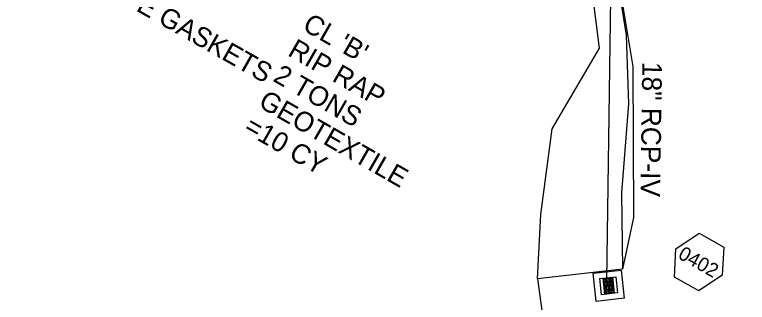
# Model space of a CAD drawing. Extents: x 1116825 to 1117461, y 843538 to 843929.
# Drawn here: x 1116903.7 to 1117034.1, y 843652.8 to 843703.9 of the extents above; entities that cross this region are included whole.
import ezdxf

# ---------------------------------------------------------------- set-up
doc = ezdxf.new("R2010")
doc.units = 0
for name, color, linetype in [('Exist Plan Preparation Watershed Blue', 7, 'Continuous'), ('Exist Plan Preparation Watershed Red', 7, 'Continuous'), ('Prop Drainage Structure Box Number Symbol CELL', 7, 'Continuous'), ('Prop Drainage Structure Drop Inlet Grate 2 Wide Slots and Flat Grates 840 20 TB CELL', 7, 'Continuous'), ('Prop Drainage Structure Pipe CSP Rod and Lug with Sleeve Gaskets Label', 7, 'Continuous'), ('Prop Drainage Structure Pipe RCP 18in Class IV', 7, 'Continuous'), ('Prop Drainage Structure Pipe RCP 18in Class IV Label', 7, 'Continuous'), ('Prop Drainage Structure Plot Symbol 20 Scale', 7, 'Continuous'), ('Prop Drainage Structure Plot Symbol 50 Scale', 7, 'Continuous'), ('Prop Erosion Rip Rap Pad at Outlet Label', 7, 'Continuous')]:
    doc.layers.add(name, color=color, linetype=linetype)

msp = doc.modelspace()

# ---------------------------------------------------------------- linework, layer by layer
at = {"layer": 'Exist Plan Preparation Watershed Blue'}
msp.add_lwpolyline([(1117011.88, 843658.68), (1116996.78, 843656.94), (1116997.38, 843668.37), (1116999.37, 843683.65), (1117007.83, 843698), (1117005.84, 843713.49), (1117010.39, 843713.99), (1117012.55, 843700.29), (1117012.98, 843688.08), (1117011.7, 843672.23)], close=True, dxfattribs=at)
at = {"layer": 'Exist Plan Preparation Watershed Red'}
msp.add_lwpolyline([(1117010.41, 843714.72), (1117013.74, 843694.71), (1117013.85, 843667.87), (1117011.88, 843658.68), (1116996.78, 843656.94), (1116999.95, 843633.96), (1117011.91, 843596.88), (1117025.61, 843575.89), (1117048.71, 843550.16), (1117064.03, 843538.25), (1117084.77, 843547.62), (1117217.35, 843572.44), (1117328.84, 843554.91), (1117432.93, 843571.69), (1117450.5, 843607.65), (1117450.73, 843646.27), (1117460.85, 843746.89), (1117431.96, 843772.25), (1117401.49, 843797.45), (1117287.63, 843757.83), (1117159.59, 843729.38)], close=True, dxfattribs=at)
at = {"layer": 'Prop Drainage Structure Box Number Symbol CELL'}
msp.add_lwpolyline([(1117025.57, 843665.04), (1117029.92, 843662.58), (1117029.66, 843657.58), (1117025.51, 843654.79), (1117021.16, 843657.26), (1117021.42, 843662.25), (1117025.57, 843665.04)], dxfattribs=at)
at = {"layer": 'Prop Drainage Structure Drop Inlet Grate 2 Wide Slots and Flat Grates 840 20 TB CELL'}
for p, q in [((1117009.28, 843657.14), (1117009.28, 843657.14)), ((1117008.6, 843655.62), (1117008.6, 843655.62)), ((1117009.44, 843655.71), (1117009.44, 843655.71)), ((1117010.27, 843655.8), (1117010.27, 843655.8)), ((1117009.59, 843654.28), (1117009.59, 843654.28))]:
    msp.add_line(p, q, dxfattribs=at)
for points in [[(1117010.12, 843657.23), (1117010.43, 843654.37), (1117008.76, 843654.19), (1117008.45, 843657.05), (1117010.12, 843657.23)], [(1117010.08, 843657.18), (1117010.38, 843654.41), (1117008.8, 843654.23), (1117008.5, 843657.01), (1117010.08, 843657.18)], [(1117010.07, 843657.17), (1117010.22, 843655.8), (1117008.65, 843655.63), (1117008.5, 843657), (1117010.07, 843657.17)], [(1117008.84, 843656.98), (1117008.9, 843656.38), (1117008.71, 843656.36), (1117008.64, 843656.96), (1117008.84, 843656.98)], [(1117008.91, 843656.32), (1117008.98, 843655.73), (1117008.78, 843655.7), (1117008.72, 843656.3), (1117008.91, 843656.32)], [(1117009.11, 843657.01), (1117009.18, 843656.41), (1117008.99, 843656.39), (1117008.92, 843656.99), (1117009.11, 843657.01)], [(1117009.19, 843656.35), (1117009.25, 843655.76), (1117009.06, 843655.73), (1117008.99, 843656.33), (1117009.19, 843656.35)], [(1117009.39, 843657.04), (1117009.46, 843656.44), (1117009.26, 843656.42), (1117009.2, 843657.02), (1117009.39, 843657.04)], [(1117009.46, 843656.38), (1117009.53, 843655.79), (1117009.33, 843655.76), (1117009.27, 843656.36), (1117009.46, 843656.38)], [(1117009.67, 843657.07), (1117009.73, 843656.47), (1117009.54, 843656.45), (1117009.47, 843657.05), (1117009.67, 843657.07)], [(1117009.74, 843656.41), (1117009.8, 843655.82), (1117009.61, 843655.79), (1117009.54, 843656.39), (1117009.74, 843656.41)], [(1117009.94, 843657.1), (1117010.01, 843656.5), (1117009.81, 843656.48), (1117009.75, 843657.08), (1117009.94, 843657.1)], [(1117010.01, 843656.44), (1117010.08, 843655.85), (1117009.89, 843655.82), (1117009.82, 843656.42), (1117010.01, 843656.44)], [(1117010.22, 843655.79), (1117010.37, 843654.41), (1117008.81, 843654.24), (1117008.66, 843655.61), (1117010.22, 843655.79)], [(1117008.99, 843655.59), (1117009.06, 843654.99), (1117008.86, 843654.97), (1117008.8, 843655.57), (1117008.99, 843655.59)], [(1117009.27, 843655.62), (1117009.33, 843655.02), (1117009.14, 843655), (1117009.07, 843655.6), (1117009.27, 843655.62)], [(1117009.34, 843654.97), (1117009.4, 843654.37), (1117009.21, 843654.35), (1117009.14, 843654.94), (1117009.34, 843654.97)], [(1117009.54, 843655.65), (1117009.61, 843655.06), (1117009.41, 843655.03), (1117009.35, 843655.63), (1117009.54, 843655.65)], [(1117009.61, 843655), (1117009.68, 843654.4), (1117009.49, 843654.38), (1117009.42, 843654.97), (1117009.61, 843655)], [(1117009.82, 843655.68), (1117009.88, 843655.09), (1117009.69, 843655.06), (1117009.62, 843655.66), (1117009.82, 843655.68)], [(1117009.82, 843655.68), (1117009.88, 843655.09), (1117009.69, 843655.06), (1117009.62, 843655.66), (1117009.82, 843655.68)], [(1117009.89, 843655.03), (1117009.95, 843654.43), (1117009.76, 843654.41), (1117009.7, 843655), (1117009.89, 843655.03)], [(1117009.89, 843655.03), (1117009.95, 843654.43), (1117009.76, 843654.41), (1117009.7, 843655), (1117009.89, 843655.03)], [(1117010.09, 843655.71), (1117010.16, 843655.12), (1117009.97, 843655.09), (1117009.9, 843655.69), (1117010.09, 843655.71)], [(1117010.17, 843655.06), (1117010.23, 843654.46), (1117010.04, 843654.44), (1117009.97, 843655.03), (1117010.17, 843655.06)], [(1117009.06, 843654.94), (1117009.13, 843654.34), (1117008.93, 843654.32), (1117008.87, 843654.91), (1117009.06, 843654.94)]]:
    msp.add_lwpolyline(points, dxfattribs=at)
at = {"layer": 'Prop Drainage Structure Pipe RCP 18in Class IV'}
msp.add_line((1117009.13, 843656.65), (1117009.89, 843710.22), dxfattribs=at)
at = {"layer": 'Prop Drainage Structure Plot Symbol 20 Scale'}
msp.add_lwpolyline([(1117010.71, 843657.3), (1117011.03, 843654.43), (1117008.16, 843654.12), (1117007.85, 843656.98)], close=True, dxfattribs=at)
at = {"layer": 'Prop Drainage Structure Plot Symbol 50 Scale'}
msp.add_lwpolyline([(1117011.67, 843658.49), (1117012.22, 843653.48), (1117007.21, 843652.93), (1117006.66, 843657.94)], close=True, dxfattribs=at)

# ---------------------------------------------------------------- texts
at = {"layer": 'Prop Drainage Structure Box Number Symbol CELL'}
msp.add_text('0402', height=2.5, rotation=330.4885, dxfattribs=at).set_placement((1117021.61, 843660.7))
at = {"layer": 'Prop Drainage Structure Pipe CSP Rod and Lug with Sleeve Gaskets Label'}
msp.add_text('WITH SLEEVE GASKETS', height=3.5, rotation=330.4885, dxfattribs=at).set_placement((1116900.52, 843718.69))
at = {"layer": 'Prop Drainage Structure Pipe RCP 18in Class IV Label'}
msp.add_text('18" RCP-IV ', height=3.5, rotation=269.1819, dxfattribs=at).set_placement((1117015.44, 843695.56))
at = {"layer": 'Prop Erosion Rip Rap Pad at Outlet Label'}
for s, p in [("CL 'B'", (1116954.76, 843701.33)), ('RIP RAP', (1116952.15, 843696.77)), ('2 TONS', (1116949.53, 843692.22)), ('GEOTEXTILE', (1116946.92, 843687.67)), ('=10 CY', (1116944.31, 843683.11))]:
    msp.add_text(s, height=3.5, rotation=330.1474, dxfattribs=at).set_placement(p)

doc.saveas('drawing.dxf')
